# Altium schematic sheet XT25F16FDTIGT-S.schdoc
size 127 x 101 mm
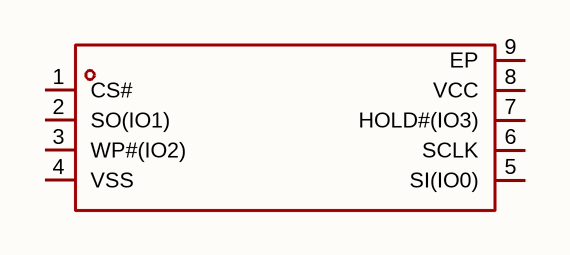
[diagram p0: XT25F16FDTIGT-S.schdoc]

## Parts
U?  xt25f16fdtigt-s  [UDFN-8_L3.0-W2.0-P0.50-BL-EP]  (value not drawn)

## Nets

Not connected (* = marked no-connect by the designer): U? 1(CS#) 2(SO(IO1)) 3(WP#(IO2)) 4(VSS) 5(SI(IO0)) 6(SCLK) 7(HOLD#(IO3)) 8(VCC) 9(EP)

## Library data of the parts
U? = xt25f16fdtigt-s: 接口类型:SPI;存储容量:16Mbit;时钟频率(fc):133MHz;; Manufacturer: XTX(芯天下); AddInBom: yes; ModelId: d79539ce19f74b038ba0aa9260016de1; ModelTransform: 78.74,118.11,0,0,0,0,0,0,0; Interface: SPI; Memory Size: 16Mbit; Clock Frequency: 133MHz; Voltage - Supply: 2.3V~3.6V; Standby Supply Current: 0.3uA; Program / Erase Cycles: 100000次; Page Programming Time (Tpp): 400us; Block Erase Time(tBE): 120ms@(32KB)；150ms@(64KB); Data Retention - TDR (Year): 20年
